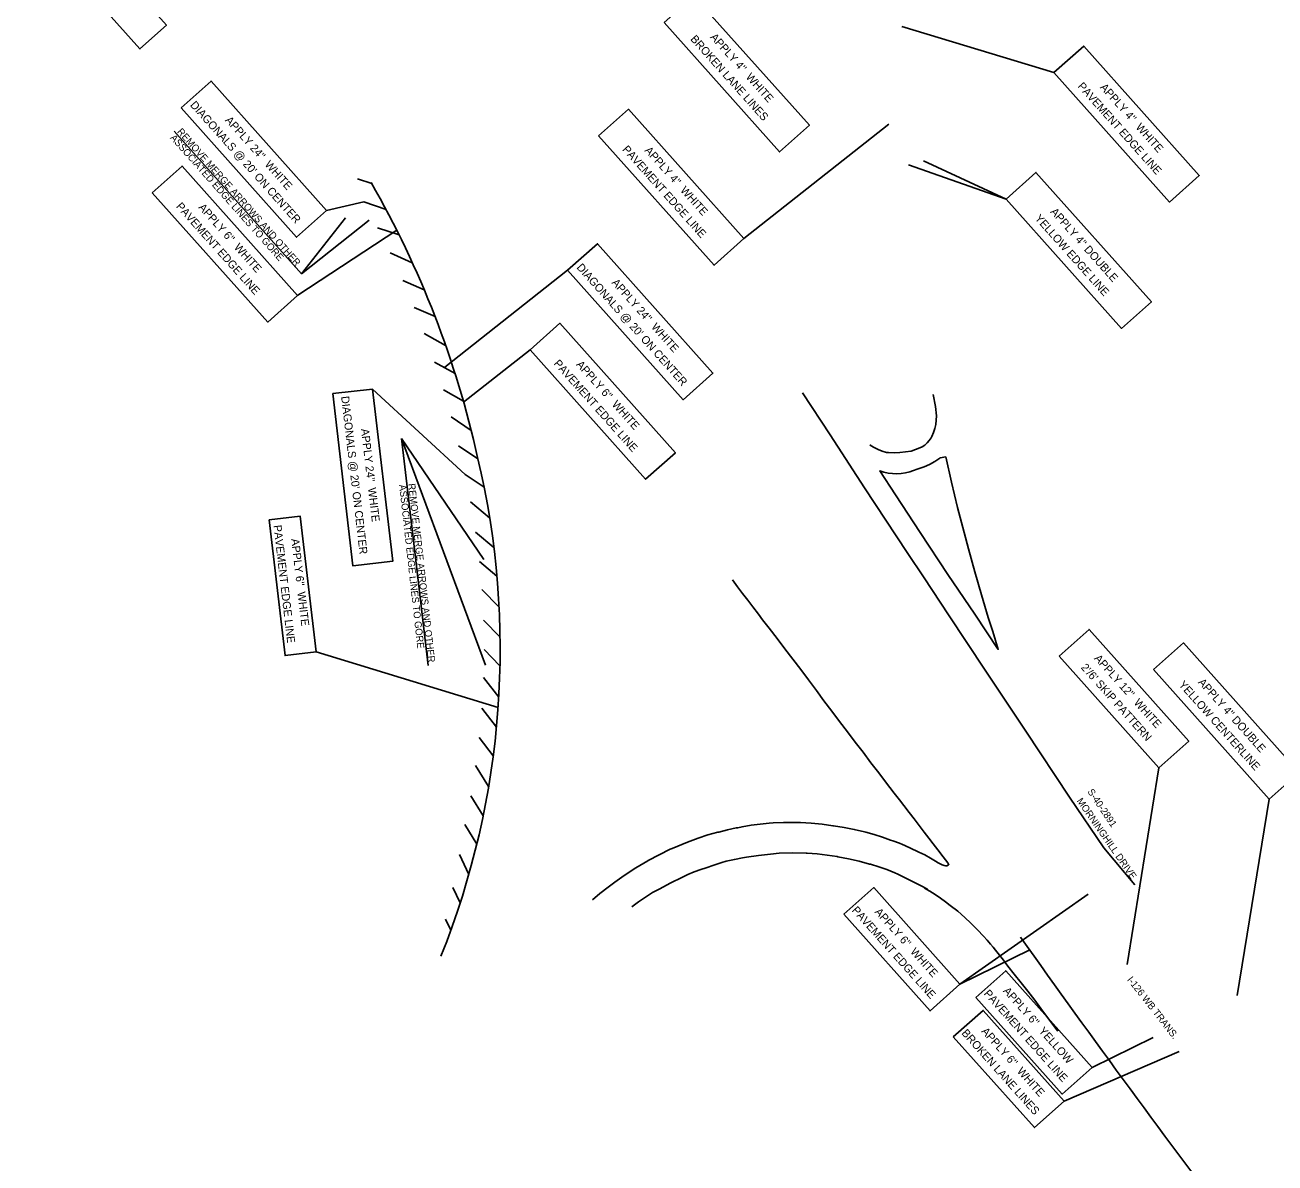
# Model space of a CAD drawing. Extents: x 1966013 to 1974896, y 789499 to 804826.
# Drawn here: x 1968605 to 1969854, y 797784 to 798921 of the extents above; entities that cross this region are included whole.
import ezdxf

# ---------------------------------------------------------------- set-up
doc = ezdxf.new("R2010")
doc.units = 0
for name, color, linetype in [('RD_EX_H2O_BlueLn', 7, 'Continuous'), ('RD_HC_Data_Rel', 7, 'Continuous'), ('RD_PD_ALT5_CL', 7, 'Continuous'), ('RD_PD_Final_Cl', 7, 'Continuous'), ('RD_PD_MedBWall', 7, 'Continuous')]:
    doc.layers.add(name, color=color, linetype=linetype)

msp = doc.modelspace()

# ---------------------------------------------------------------- linework, layer by layer
at = {"layer": 'RD_EX_H2O_BlueLn'}
for p, q in [((1969481.1, 798919.3), (1969633.2, 798873.1)), ((1969323.4, 798707.3), (1969468.3, 798821.6)), ((1968754, 798814.5), (1968881.1, 798672.2)), ((1969487.8, 798781), (1969585.4, 798746.8)), ((1969502.8, 798784.9), (1969585.4, 798746.8)), ((1968943.4, 798743.9), (1968906.2, 798735.3)), ((1968925.1, 798728.2), (1968881.1, 798672.2)), ((1968877.7, 798650.8), (1968976.5, 798715.6)), ((1968881.1, 798672.2), (1968949, 798725.8)), ((1969024.5, 798578.8), (1969147.2, 798675.6)), ((1969043.2, 798543.7), (1969109.7, 798596.1)), ((1969044.7, 798471.7), (1968952.1, 798557)), ((1968981.2, 798507.4), (1969065.2, 798281.1)), ((1968981.2, 798507.4), (1969063.4, 798386.6)), ((1968981.2, 798507.4), (1969007.9, 798280.7)), ((1968895.8, 798294.3), (1969077.7, 798238.7)), ((1969706.3, 797982), (1969738.2, 798178.5)), ((1969816.5, 797950.9), (1969848.4, 798147.3)), ((1969683, 798098.7), (1969714.2, 798061.7)), ((1969539.3, 797962.3), (1969667.5, 798052.4)), ((1969539.3, 797962.3), (1969609, 797996.7)), ((1969671.3, 797879.1), (1969732.3, 797909.2)), ((1969643.5, 797845.6), (1969758.4, 797895.2))]:
    msp.add_line(p, q, dxfattribs=at)
for points in [[(1968604.9, 799025.4), (1968719.8, 798896.8), (1968746.3, 798920.4), (1968631.4, 799049.1)], [(1969243.7, 798923.2), (1969359.1, 798793.9), (1969388.9, 798820.5), (1969273.5, 798949.8)], [(1969633.2, 798873.1), (1969748.7, 798743.8), (1969778.5, 798770.4), (1969663.1, 798899.7)], [(1968760.9, 798837.9), (1968876.4, 798708.6), (1968906.2, 798735.3), (1968790.8, 798864.6)], [(1969178.1, 798810), (1969293.6, 798680.7), (1969323.4, 798707.3), (1969208, 798836.6)], [(1968732.1, 798753.1), (1968847.5, 798623.8), (1968877.4, 798650.5), (1968761.9, 798779.8)], [(1969585.4, 798746.8), (1969700.8, 798617.5), (1969730.6, 798644.1), (1969615.2, 798773.4)], [(1969147.2, 798675.6), (1969262.7, 798546.3), (1969292.5, 798572.9), (1969177.1, 798702.2)], [(1969109.7, 798596.1), (1969225.1, 798466.8), (1969255, 798493.4), (1969139.5, 798622.7)], [(1968912.4, 798552.4), (1968932.7, 798380.2), (1968972.4, 798384.9), (1968952.1, 798557)], [(1968848.9, 798426.4), (1968864.9, 798290.6), (1968895.8, 798294.3), (1968879.9, 798430)], [(1969638.4, 798290.2), (1969738.2, 798178.5), (1969768, 798205.1), (1969668.3, 798316.8)], [(1969732.9, 798276.6), (1969848.4, 798147.3), (1969878.2, 798174), (1969762.8, 798303.3)], [(1969423.3, 798032.2), (1969509.5, 797935.6), (1969539.3, 797962.3), (1969453.1, 798058.8)], [(1969555.2, 797949), (1969641.5, 797852.5), (1969671.3, 797879.1), (1969585.1, 797975.7)], [(1969532.7, 797909.6), (1969613.7, 797819), (1969643.5, 797845.6), (1969562.6, 797936.2)]]:
    msp.add_lwpolyline(points, close=True, dxfattribs=at)
for points in [[(1969382, 798553.3), (1969409.5, 798511.2), (1969443.9, 798458.2), (1969486.7, 798393.5), (1969503.5, 798368.2), (1969527.9, 798331.3), (1969564.5, 798276.2), (1969605, 798215), (1969648.8, 798149.3), (1969683, 798098.7)], [(1969512.7, 798551.5), (1969514.8, 798539.5), (1969515.9, 798530.2), (1969515.7, 798525.9), (1969515.2, 798521.7), (1969514.2, 798517.5), (1969512.9, 798513.4), (1969511.2, 798509.4), (1969510.5, 798508.1), (1969508.7, 798505.4), (1969506.5, 798503.1), (1969504.1, 798501), (1969501.4, 798499.2), (1969499.2, 798498.1), (1969490.6, 798495), (1969485, 798494.1), (1969479.3, 798493.5), (1969473.6, 798493.3), (1969467.9, 798493.5), (1969466, 798493.6), (1969461.7, 798494.9), (1969457.6, 798496.5), (1969453.6, 798498.5), (1969450.5, 798500.3), (1969449.3, 798501.3)], [(1969525.2, 798489.3), (1969530.9, 798464), (1969537, 798438.7), (1969543.5, 798413.5), (1969547.9, 798397.2), (1969554.1, 798374.3), (1969560.7, 798351.4), (1969567.6, 798328.7), (1969572.1, 798314.8), (1969577.6, 798296.8), (1969554.3, 798331.9), (1969527.2, 798371.8), (1969499.6, 798413.6), (1969474.8, 798451.3), (1969459.1, 798475.1), (1969463.2, 798473.9), (1969467.5, 798473), (1969471.9, 798472.5), (1969476.3, 798472.4), (1969480.6, 798472.7), (1969484.9, 798473.3), (1969489.2, 798474.4), (1969491.9, 798475.3), (1969497.7, 798477.1), (1969503.4, 798479.2), (1969508.9, 798481.7), (1969514.2, 798484.6), (1969519.3, 798487.8), (1969519.7, 798488.1), (1969525.2, 798489.3)], [(1969311.9, 798366.2), (1969317, 798359.3), (1969321.9, 798352.8), (1969327.2, 798346), (1969332.2, 798339.5), (1969338.1, 798331.9), (1969342.1, 798326.5), (1969348.8, 798317.9), (1969356.6, 798307.7), (1969364.4, 798297.5), (1969372.4, 798287), (1969380.2, 798276.7), (1969388, 798266.3), (1969395.8, 798255.9), (1969403.4, 798245.6), (1969411.3, 798235.1), (1969419.1, 798224.7), (1969426.9, 798214.6), (1969434.7, 798204.2), (1969442.5, 798194), (1969450.4, 798183.6), (1969458.3, 798173.4), (1969465, 798164.6), (1969469.2, 798159), (1969473.6, 798153.3), (1969479, 798146.4), (1969483.3, 798140.8), (1969488.7, 798133.9), (1969493.5, 798127.4), (1969498.4, 798121), (1969503.5, 798114.4), (1969508.3, 798108.2), (1969512.4, 798102.7), (1969517.2, 798096.6), (1969522.5, 798089.7), (1969527.2, 798083.7), (1969528, 798082.3), (1969528.1, 798082.1), (1969528.1, 798081.9), (1969528, 798081.7), (1969526.2, 798080.7), (1969525.9, 798080.6), (1969525.6, 798080.5), (1969524.9, 798080.7), (1969523.6, 798080.9), (1969521.6, 798081.6), (1969517, 798084), (1969516.4, 798084.4), (1969509.9, 798088.4), (1969504.2, 798091.5), (1969498.2, 798094.4), (1969489.2, 798098.5), (1969481.1, 798102.2), (1969477.8, 798103.5)], [(1969172.1, 798046.6), (1969179.5, 798052.9), (1969187.6, 798059.3), (1969194.4, 798064.2), (1969203.7, 798070.9), (1969215.4, 798078.5), (1969227.3, 798085.7), (1969227.7, 798085.9), (1969238.6, 798091.6), (1969249.7, 798097.1), (1969251.6, 798098), (1969266.9, 798104.2), (1969277.6, 798108.4), (1969287.5, 798111.5), (1969297.5, 798114.2), (1969298.4, 798114.4), (1969306.9, 798116.6), (1969315.6, 798118.4), (1969317.3, 798118.7), (1969321.6, 798119.6), (1969330.5, 798121.2), (1969339.5, 798122.3), (1969348.5, 798123.1), (1969352.7, 798123.4), (1969363.1, 798123.9), (1969373.5, 798124), (1969379.9, 798123.8), (1969390.7, 798123.2), (1969401.5, 798122.2), (1969412.3, 798120.7), (1969413.1, 798120.6), (1969423.5, 798119), (1969433.7, 798117), (1969443.9, 798114.6), (1969445.1, 798114.3), (1969453.5, 798112), (1969461.8, 798109.4), (1969470, 798106.3), (1969472.2, 798105.5), (1969479, 798103.1)], [(1969211.5, 798039.6), (1969218.2, 798044.6), (1969225.1, 798049.4), (1969232.2, 798053.8), (1969238.6, 798057.4), (1969250.5, 798063.5), (1969261.2, 798069), (1969267.3, 798072), (1969273.7, 798074.7), (1969280.2, 798077), (1969285.6, 798078.6), (1969293.3, 798081.4), (1969301.2, 798083.8), (1969305.8, 798085.1), (1969313.9, 798087), (1969322, 798088.5), (1969325.9, 798089.1), (1969337.9, 798091), (1969349.9, 798092.4), (1969358.8, 798093.2), (1969372.1, 798093.5), (1969385.5, 798093.4), (1969386.5, 798093.4), (1969396.6, 798092.6), (1969406.6, 798091.4), (1969416.6, 798089.8), (1969417.2, 798089.7), (1969427.8, 798087.7), (1969438.5, 798085.2), (1969449, 798082.4), (1969449.9, 798082.1), (1969458.2, 798079.6), (1969466.3, 798076.8), (1969474.3, 798073.5), (1969477.1, 798072.3), (1969491.8, 798064.9), (1969492, 798064.8), (1969499.9, 798061), (1969506.8, 798057.2)], [(1969504, 798058.4), (1969509.2, 798055.2), (1969514.6, 798051.8), (1969519.8, 798048.2), (1969525, 798044.5), (1969529.5, 798041), (1969537.2, 798035.2), (1969540.6, 798032.4), (1969544.4, 798028.8), (1969550, 798023.5), (1969556.8, 798016.6), (1969562.8, 798010.3), (1969566.5, 798006.2), (1969569.8, 798002.4), (1969572.5, 797999.4), (1969575, 797996.3), (1969577.6, 797993), (1969582.7, 797986.4), (1969587.1, 797980.5), (1969593.6, 797972.2), (1969600.6, 797963.6), (1969607.2, 797955.3), (1969614, 797946.5), (1969620.2, 797938.1), (1969626.9, 797929.2), (1969637.1, 797915.5)]]:
    msp.add_lwpolyline(points, dxfattribs=at)
at = {"layer": 'RD_HC_Data_Rel'}
for p, q in [((1968937.2, 798767.1), (1968951.4, 798762.3)), ((1968943.4, 798743.9), (1968965.7, 798736.4)), ((1968957.2, 798718.2), (1968978.8, 798710.9)), ((1968969.7, 798693), (1968992, 798683.2)), ((1968982.4, 798665.5), (1969003.9, 798656)), ((1968993.8, 798638.6), (1969014.7, 798629.4)), ((1969004, 798612.5), (1969025.3, 798600.6)), ((1969014.1, 798583.9), (1969034.7, 798572.5)), ((1969023, 798556.1), (1969043, 798545)), ((1969030.8, 798529.1), (1969050.8, 798515.7)), ((1969038.2, 798500.1), (1969057.6, 798487.2)), ((1969044.7, 798471.7), (1969063.7, 798459.1)), ((1969050.3, 798444.2), (1969069.3, 798428.3)), ((1969055.3, 798414), (1969073.5, 798398.7)), ((1969059, 798384.8), (1969076.5, 798370.1)), ((1969061.5, 798356.8), (1969078.7, 798338.9)), ((1969063.2, 798326.2), (1969079.7, 798309.1)), ((1969063.7, 798296.8), (1969079.6, 798280.3)), ((1969063.2, 798268.7), (1969078.3, 798249.1)), ((1969061.6, 798238.1), (1969076.1, 798219.2)), ((1969058.9, 798208.7), (1969072.8, 798190.6)), ((1969055.3, 798180.9), (1969068.2, 798159.8)), ((1969050.4, 798150.6), (1969062.7, 798130.4)), ((1969044.5, 798121.8), (1969056.4, 798102.3)), ((1969039.2, 798091.8), (1969048.4, 798072.1)), ((1969032.6, 798058.8), (1969039.8, 798043.5)), ((1969025.2, 798027.3), (1969030.4, 798016.2))]:
    msp.add_line(p, q, dxfattribs=at)
at = {"layer": 'RD_PD_ALT5_CL'}
for centre, radius, start, end in [((1968103.7, 798277.2), 976.7, 12.5047, 29.8558), ((1968254.4, 798297.2), 825.4, 338.167, 13.4097), ((1978987, 804673.3), 11512, 215.37035, 217.23394)]:
    msp.add_arc(centre, radius, start, end, dxfattribs=at)

# ---------------------------------------------------------------- texts
at = {"layer": 'RD_EX_H2O_BlueLn'}
for s, height, rotation, p in [('BROKEN LANE LINES', 8, 311.7606, (1969269.4, 798906.3)), ("APPLY 4''  WHITE", 8, 311.7606, (1969289.2, 798908.2)), ('PAVEMENT EDGE LINE', 8, 311.7606, (1969656.5, 798859.1)), ("APPLY 4''  WHITE", 8, 311.7606, (1969678.8, 798858.1)), ("DIAGONALS @ 20' ON CENTER", 8, 311.7606, (1968769.4, 798840.4)), ("APPLY 24''  WHITE", 8, 311.7606, (1968804.4, 798825.2)), ('REMOVE MERGE ARROWS AND OTHER', 7, 311.5333, (1968756.5, 798813.8)), ('ASSOCIATED EDGE LINES TO GORE', 7, 311.5333, (1968749.6, 798807.7)), ('PAVEMENT EDGE LINE', 8, 311.7606, (1969201.4, 798796)), ("APPLY 4''  WHITE", 8, 311.7606, (1969223.7, 798795)), ('PAVEMENT EDGE LINE', 8, 311.7606, (1968755.4, 798739.1)), ("APPLY 6''  WHITE", 8, 311.7606, (1968777.7, 798738.1)), ('YELLOW EDGE LINE', 7.999, 311.7606, (1969613.6, 798727.2)), ("APPLY 4'' DOUBLE", 7.999, 311.7606, (1969629.2, 798733.7)), ("DIAGONALS @ 20' ON CENTER", 8, 311.7606, (1969155.7, 798678.1)), ("APPLY 24''  WHITE", 8, 311.7606, (1969190.7, 798662.9)), ('PAVEMENT EDGE LINE', 8, 311.7606, (1969132.9, 798582.1)), ("APPLY 6''  WHITE", 8, 311.7606, (1969155.3, 798581.1)), ("DIAGONALS @ 20' ON CENTER", 8, 276.7064, (1968920.8, 798549.5)), ("APPLY 24''  WHITE", 8, 276.7064, (1968940.7, 798517)), ('ASSOCIATED EDGE LINES TO GORE', 7, 276.3743, (1968978.8, 798461.2)), ('REMOVE MERGE ARROWS AND OTHER', 7, 276.3743, (1968987.9, 798462.3)), ('PAVEMENT EDGE LINE', 8, 276.7064, (1968853.2, 798420.7)), ("APPLY 6''  WHITE", 8, 276.7064, (1968870.9, 798407.1)), ("APPLY 12''  WHITE", 7.999, 311.7608, (1969673, 798287.5)), ("2'/6' SKIP PATTERN", 7.999, 311.7608, (1969659.7, 798278.4)), ('YELLOW CENTERLINE', 7.999, 311.7606, (1969757.4, 798261.2)), ("APPLY 4'' DOUBLE", 7.999, 311.7606, (1969776.8, 798263.6)), ('PAVEMENT EDGE LINE', 8, 311.7606, (1969430.8, 798035.8)), ("APPLY 6''  WHITE", 8, 311.7606, (1969453.6, 798034.2)), ('PAVEMENT EDGE LINE', 8, 311.7606, (1969562.7, 797952.6)), ("APPLY 6''  YELLOW", 8, 311.7606, (1969581.9, 797955.2)), ('BROKEN LANE LINES', 8, 311.7606, (1969540.4, 797913.1)), ("APPLY 6''  WHITE", 8, 311.7606, (1969560.2, 797914.9))]:
    msp.add_text(s, height=height, rotation=rotation, dxfattribs=at).set_placement(p)
at = {"layer": 'RD_PD_Final_Cl'}
msp.add_text('S-40-2891', height=7, rotation=304.0279, dxfattribs=at).set_placement((1969666.4, 798154.7))
at = {"layer": 'RD_PD_MedBWall'}
for s, rotation, p in [('MORNINGHILL DRIVE', 304.822, (1969655.7, 798145.4)), ('I-126 WB TRANS.', 307.9923, (1969706, 797966.7))]:
    msp.add_text(s, height=7, rotation=rotation, dxfattribs=at).set_placement(p)

doc.saveas('drawing.dxf')
